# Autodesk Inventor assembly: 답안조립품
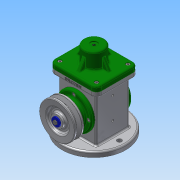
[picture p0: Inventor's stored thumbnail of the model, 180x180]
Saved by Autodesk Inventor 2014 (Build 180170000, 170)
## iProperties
Created: 2018-10
Part Number: 답안조립품
Document SubType Name: Assembly
Designer: Administrator
Author: Administrator
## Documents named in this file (18)
- C:\Users\Administrator\Desktop\481007V1041\답안조립품.iam
- C:\Users\Administrator\Desktop\481007V1041\본체.ipt
- C:\Users\Administrator\Desktop\481007V1041\E-링.ipt
- C:\Users\Administrator\Desktop\481007V1041\V-벨트풀리.ipt
- C:\Users\Administrator\Desktop\481007V1041\덮개.ipt
- C:\Users\Administrator\Desktop\481007V1041\뒤커버.ipt
- C:\Users\Administrator\Desktop\481007V1041\링크.ipt
- C:\Users\Administrator\Desktop\481007V1041\베어링 17 x 40 x 12.ipt
- C:\Users\Administrator\Desktop\481007V1041\볼트 M4 x 8.ipt
- C:\Users\Administrator\Desktop\481007V1041\볼트 M4 x 10.ipt
- C:\Users\Administrator\Desktop\481007V1041\슬라이더.ipt
- C:\Users\Administrator\Desktop\481007V1041\앞커버.ipt
- C:\Users\Administrator\Desktop\481007V1041\오일 실 17 30 8.ipt
- C:\Users\Administrator\Desktop\481007V1041\와셔 4x16.ipt
- C:\Users\Administrator\Desktop\481007V1041\클레비스 핀 6 x 22.ipt
- 클레비스 핀 6 x 22.ipt
- C:\Users\Administrator\Desktop\481007V1041\키 4 x 4 x 12.ipt
- C:\Users\Administrator\Desktop\481007V1041\편심축.ipt
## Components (2 placed, 2 different names)
1. E-링:1 — 각도:4
2. V-벨트풀리:1 — 각도:2
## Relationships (2: Angle 2)
- 각도:2 [Angle]: V-벨트풀리:1
- 각도:4 [Angle]: E-링:1
